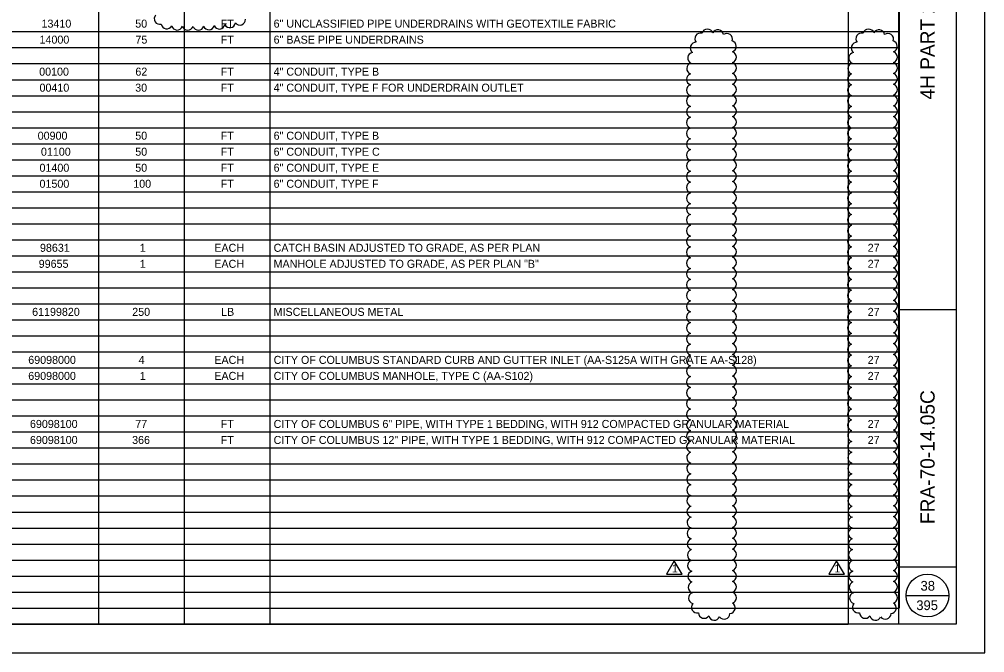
# Model space of a CAD drawing. Extents: x 0 to 34, y 0 to 22.
# Drawn here: x 17.12 to 34, y 0 to 11.08 of the extents above; entities that cross this region are included whole.
import ezdxf

# ---------------------------------------------------------------- set-up
doc = ezdxf.new("R2010")
doc.units = 0
for name, color, linetype in [('SH_Border', 7, 'Continuous'), ('SH_Cut_Line', 7, 'Continuous'), ('SH_Data', 7, 'Continuous'), ('SH_Text', 7, 'Continuous'), ('TX_P_1000', 7, 'Continuous')]:
    doc.layers.add(name, color=color, linetype=linetype)

msp = doc.modelspace()

# ---------------------------------------------------------------- linework, layer by layer
at = {"layer": 'SH_Border'}
for p, q in [((32.5, 0.5), (32.5, 21.5)), ((32.5, 6), (33.5, 6)), ((32.5, 1.5), (33.5, 1.5))]:
    msp.add_line(p, q, dxfattribs=at)
msp.add_lwpolyline([(2, 21.5), (33.5, 21.5), (33.5, 0.5), (2, 0.5)], close=True, dxfattribs=at)
at = {"layer": 'SH_Cut_Line'}
msp.add_lwpolyline([(0, 0), (34, 0), (34, 22), (0, 22)], close=True, dxfattribs=at)
at = {"layer": 'SH_Data'}
for p, q in [((18.504, 21.5), (18.504, 0.5)), ((20.002, 21.5), (20.002, 0.5)), ((21.501, 21.5), (21.501, 0.5)), ((31.614, 21.5), (31.614, 0.5)), ((32.504, 21.5), (32.504, 0.78)), ((2, 10.86), (32.504, 10.86)), ((2, 10.58), (32.504, 10.58)), ((2, 10.3), (32.504, 10.3)), ((2, 10.02), (32.504, 10.02)), ((2, 9.74), (32.504, 9.74)), ((2, 9.46), (32.504, 9.46)), ((2, 9.18), (32.504, 9.18)), ((2, 8.9), (32.504, 8.9)), ((2, 8.62), (32.504, 8.62)), ((2, 8.34), (32.504, 8.34)), ((2, 8.06), (32.504, 8.06)), ((2, 7.78), (32.504, 7.78)), ((2, 7.5), (32.504, 7.5)), ((2, 7.22), (32.504, 7.22)), ((2, 6.94), (32.504, 6.94)), ((2, 6.66), (32.504, 6.66)), ((2, 6.38), (32.504, 6.38)), ((2, 6.1), (32.504, 6.1)), ((2, 5.82), (32.504, 5.82)), ((2, 5.54), (32.504, 5.54)), ((2, 5.26), (32.504, 5.26)), ((2, 4.98), (32.504, 4.98)), ((2, 4.7), (32.504, 4.7)), ((2, 4.42), (32.504, 4.42)), ((2, 4.14), (32.504, 4.14)), ((2, 3.86), (32.504, 3.86)), ((2, 3.58), (32.504, 3.58)), ((2, 3.3), (32.504, 3.3)), ((2, 3.02), (32.504, 3.02)), ((2, 2.74), (32.504, 2.74)), ((2, 2.46), (32.504, 2.46)), ((2, 2.18), (32.504, 2.18)), ((2, 1.9), (32.504, 1.9)), ((2, 1.62), (32.504, 1.62)), ((2, 1.34), (32.504, 1.34)), ((2, 1.06), (32.504, 1.06)), ((32.625, 1), (33.375, 1)), ((2, 0.78), (32.504, 0.78)), ((2, 0.5), (31.614, 0.5))]:
    msp.add_line(p, q, dxfattribs=at)
msp.add_circle((33, 1), 0.375, dxfattribs=at)
at = {"layer": 'TX_P_1000'}
for points in [[(28.571, 1.608), (28.435, 1.372), (28.708, 1.372)], [(31.411, 1.608), (31.274, 1.372), (31.547, 1.372)]]:
    msp.add_lwpolyline(points, close=True, dxfattribs=at)
for centre, radius, start, end in [((19.578, 11.085), 0.0976, 139.2641, 284.2641), ((19.699, 11.005), 0.0976, 188.32, 333.32), ((20.62, 11.003), 0.0976, 202.8824, 347.8824), ((20.803, 11.026), 0.0976, 206.7346, 351.7346), ((20.977, 11.072), 0.0977, 217.3339, 2.3339), ((19.88, 10.986), 0.0976, 195.1082, 340.1082), ((20.065, 10.982), 0.0976, 197.1836, 342.1836), ((20.251, 10.983), 0.0976, 198.6029, 343.6029), ((20.436, 10.99), 0.0976, 200.3873, 345.3873), ((29.031, 10.736), 0.099, 74.4093, 219.4093), ((29.153, 10.805), 0.0991, 19.2496, 164.2496), ((29.336, 10.794), 0.0991, 9.041, 154.041), ((29.491, 10.729), 0.099, 340.6755, 125.6755), ((31.847, 10.736), 0.099, 74.4093, 219.4093), ((31.969, 10.805), 0.0991, 19.2496, 164.2496), ((32.152, 10.794), 0.0991, 9.041, 154.041), ((32.308, 10.729), 0.099, 340.6755, 125.6755), ((28.95, 10.574), 0.0991, 87.314, 232.314), ((29.557, 10.601), 0.0992, 288.6913, 73.6913), ((31.766, 10.574), 0.0991, 87.314, 232.314), ((32.373, 10.601), 0.0992, 288.6913, 73.6913), ((28.906, 10.398), 0.0991, 99.6335, 244.6335), ((29.559, 10.413), 0.0991, 287.5, 72.5), ((31.722, 10.398), 0.0991, 99.6335, 244.6335), ((32.375, 10.413), 0.0991, 287.5, 72.5), ((28.889, 10.213), 0.0991, 105.2456, 250.2456), ((29.559, 10.224), 0.0991, 287.5, 72.5), ((31.706, 10.213), 0.0991, 105.2456, 250.2456), ((32.375, 10.224), 0.0991, 287.5, 72.5), ((29.559, 10.035), 0.0991, 287.5, 72.5), ((32.375, 10.035), 0.0991, 287.5, 72.5), ((28.886, 10.025), 0.0991, 107.4797, 252.4797), ((31.702, 10.025), 0.0991, 107.4797, 252.4797), ((28.885, 9.836), 0.0991, 107.5, 252.5), ((29.559, 9.846), 0.0991, 287.5, 72.5), ((31.702, 9.836), 0.0991, 107.5, 252.5), ((32.375, 9.846), 0.0991, 287.5, 72.5), ((28.885, 9.647), 0.0991, 107.5, 252.5), ((29.559, 9.657), 0.0991, 287.5, 72.5), ((31.702, 9.647), 0.0991, 107.5, 252.5), ((32.375, 9.657), 0.0991, 287.5, 72.5), ((28.885, 9.458), 0.0991, 107.5, 252.5), ((29.559, 9.468), 0.0991, 287.5, 72.5), ((31.702, 9.458), 0.0991, 107.5, 252.5), ((32.375, 9.468), 0.0991, 287.5, 72.5), ((28.885, 9.269), 0.0991, 107.5, 252.5), ((29.559, 9.279), 0.0991, 287.5, 72.5), ((31.702, 9.269), 0.0991, 107.5, 252.5), ((32.375, 9.279), 0.0991, 287.5, 72.5), ((28.885, 9.08), 0.0991, 107.5, 252.5), ((29.559, 9.09), 0.0991, 287.5, 72.5), ((31.702, 9.08), 0.0991, 107.5, 252.5), ((32.375, 9.09), 0.0991, 287.5, 72.5), ((28.885, 8.891), 0.0991, 107.5, 252.5), ((29.559, 8.901), 0.0991, 287.5, 72.5), ((31.702, 8.891), 0.0991, 107.5, 252.5), ((32.375, 8.901), 0.0991, 287.5, 72.5), ((28.885, 8.702), 0.0991, 107.5, 252.5), ((29.559, 8.712), 0.0991, 287.5, 72.5), ((31.702, 8.702), 0.0991, 107.5, 252.5), ((32.375, 8.712), 0.0991, 287.5, 72.5), ((29.559, 8.523), 0.0991, 287.5, 72.5), ((32.375, 8.523), 0.0991, 287.5, 72.5), ((28.885, 8.513), 0.0991, 107.5, 252.5), ((31.702, 8.513), 0.0991, 107.5, 252.5), ((28.885, 8.324), 0.0991, 107.5, 252.5), ((29.559, 8.334), 0.0991, 287.5, 72.5), ((31.702, 8.324), 0.0991, 107.5, 252.5), ((32.375, 8.334), 0.0991, 287.5, 72.5), ((28.885, 8.135), 0.0991, 107.5, 252.5), ((29.559, 8.145), 0.0991, 287.5, 72.5), ((31.702, 8.135), 0.0991, 107.5, 252.5), ((32.375, 8.145), 0.0991, 287.5, 72.5), ((28.885, 7.946), 0.0991, 107.5, 252.5), ((29.559, 7.956), 0.0991, 287.5, 72.5), ((31.702, 7.946), 0.0991, 107.5, 252.5), ((32.375, 7.956), 0.0991, 287.5, 72.5), ((28.885, 7.757), 0.0991, 107.5, 252.5), ((29.559, 7.767), 0.0991, 287.5, 72.5), ((31.702, 7.757), 0.0991, 107.5, 252.5), ((32.375, 7.767), 0.0991, 287.5, 72.5), ((28.885, 7.568), 0.0991, 107.5, 252.5), ((29.559, 7.578), 0.0991, 287.5, 72.5), ((31.702, 7.568), 0.0991, 107.5, 252.5), ((32.375, 7.578), 0.0991, 287.5, 72.5), ((28.885, 7.379), 0.0991, 107.5, 252.5), ((29.559, 7.389), 0.0991, 287.5, 72.5), ((31.702, 7.379), 0.0991, 107.5, 252.5), ((32.375, 7.389), 0.0991, 287.5, 72.5), ((28.885, 7.19), 0.0991, 107.5, 252.5), ((29.559, 7.2), 0.0991, 287.5, 72.5), ((31.702, 7.19), 0.0991, 107.5, 252.5), ((32.375, 7.2), 0.0991, 287.5, 72.5), ((28.885, 7.001), 0.0991, 107.5, 252.5), ((29.559, 7.011), 0.0991, 287.5, 72.5), ((31.702, 7.001), 0.0991, 107.5, 252.5), ((32.375, 7.011), 0.0991, 287.5, 72.5), ((28.885, 6.812), 0.0991, 107.5, 252.5), ((29.559, 6.822), 0.0991, 287.5, 72.5), ((31.702, 6.812), 0.0991, 107.5, 252.5), ((32.375, 6.822), 0.0991, 287.5, 72.5), ((28.885, 6.623), 0.0991, 107.5, 252.5), ((29.559, 6.633), 0.0991, 287.5, 72.5), ((31.702, 6.623), 0.0991, 107.5, 252.5), ((32.375, 6.633), 0.0991, 287.5, 72.5), ((28.885, 6.434), 0.0991, 107.5, 252.5), ((29.559, 6.444), 0.0991, 287.5, 72.5), ((31.702, 6.434), 0.0991, 107.5, 252.5), ((32.375, 6.444), 0.0991, 287.5, 72.5), ((28.885, 6.245), 0.0991, 107.5, 252.5), ((29.559, 6.255), 0.0991, 287.5, 72.5), ((31.702, 6.245), 0.0991, 107.5, 252.5), ((32.375, 6.255), 0.0991, 287.5, 72.5), ((28.885, 6.056), 0.0991, 107.5, 252.5), ((29.559, 6.066), 0.0991, 287.5, 72.5), ((31.702, 6.056), 0.0991, 107.5, 252.5), ((32.375, 6.066), 0.0991, 287.5, 72.5), ((28.885, 5.867), 0.0991, 107.5, 252.5), ((29.559, 5.877), 0.0991, 287.5, 72.5), ((31.702, 5.867), 0.0991, 107.5, 252.5), ((32.375, 5.877), 0.0991, 287.5, 72.5), ((28.885, 5.678), 0.0991, 107.5, 252.5), ((29.559, 5.688), 0.0991, 287.5, 72.5), ((31.702, 5.678), 0.0991, 107.5, 252.5), ((32.375, 5.688), 0.0991, 287.5, 72.5), ((28.885, 5.489), 0.0991, 107.5, 252.5), ((29.559, 5.499), 0.0991, 287.5, 72.5), ((31.702, 5.489), 0.0991, 107.5, 252.5), ((32.375, 5.499), 0.0991, 287.5, 72.5), ((29.559, 5.31), 0.0991, 287.5, 72.5), ((32.375, 5.31), 0.0991, 287.5, 72.5), ((28.885, 5.3), 0.0991, 107.5, 252.5), ((31.702, 5.3), 0.0991, 107.5, 252.5), ((28.886, 5.111), 0.0991, 107.5091, 252.5091), ((29.559, 5.121), 0.0991, 287.5, 72.5), ((31.702, 5.111), 0.0991, 107.5091, 252.5091), ((32.375, 5.121), 0.0991, 287.5, 72.5), ((28.886, 4.922), 0.0991, 107.5258, 252.5258), ((29.559, 4.932), 0.0991, 287.5, 72.5), ((31.702, 4.922), 0.0991, 107.5258, 252.5258), ((32.375, 4.932), 0.0991, 287.5, 72.5), ((28.886, 4.733), 0.0991, 107.5437, 252.5437), ((29.559, 4.743), 0.0991, 287.5, 72.5), ((31.702, 4.733), 0.0991, 107.5437, 252.5437), ((32.375, 4.743), 0.0991, 287.5, 72.5), ((28.886, 4.544), 0.0991, 107.5629, 252.5629), ((29.559, 4.554), 0.0991, 287.5, 72.5), ((31.702, 4.544), 0.0991, 107.5629, 252.5629), ((32.375, 4.554), 0.0991, 287.5, 72.5), ((28.886, 4.355), 0.0991, 107.5836, 252.5836), ((29.559, 4.365), 0.0991, 287.5, 72.5), ((31.703, 4.355), 0.0991, 107.5836, 252.5836), ((32.375, 4.365), 0.0991, 287.5, 72.5), ((28.886, 4.166), 0.0991, 107.606, 252.606), ((29.559, 4.176), 0.0991, 287.5, 72.5), ((31.703, 4.166), 0.0991, 107.606, 252.606), ((32.375, 4.176), 0.0991, 287.5, 72.5), ((28.887, 3.977), 0.0991, 107.6303, 252.6303), ((29.559, 3.987), 0.0991, 287.5, 72.5), ((31.703, 3.977), 0.0991, 107.6303, 252.6303), ((32.375, 3.987), 0.0991, 287.5, 72.5), ((28.887, 3.788), 0.0991, 107.6568, 252.6568), ((29.559, 3.797), 0.0991, 287.5, 72.5), ((31.704, 3.788), 0.0991, 107.6568, 252.6568), ((32.375, 3.797), 0.0991, 287.5, 72.5), ((28.888, 3.599), 0.0991, 107.6859, 252.6859), ((29.559, 3.608), 0.0991, 287.5, 72.5), ((31.704, 3.599), 0.0991, 107.6859, 252.6859), ((32.375, 3.608), 0.0991, 287.5, 72.5), ((28.889, 3.41), 0.0991, 107.718, 252.718), ((29.559, 3.419), 0.0991, 287.5, 72.5), ((31.705, 3.41), 0.0991, 107.718, 252.718), ((32.375, 3.419), 0.0991, 287.5, 72.5), ((28.889, 3.221), 0.0991, 107.7537, 252.7537), ((29.559, 3.23), 0.0991, 287.5, 72.5), ((31.706, 3.221), 0.0991, 107.7537, 252.7537), ((32.375, 3.23), 0.0991, 287.5, 72.5), ((28.89, 3.032), 0.0991, 107.7938, 252.7938), ((29.559, 3.041), 0.0991, 287.5, 72.5), ((31.707, 3.032), 0.0991, 107.7938, 252.7938), ((32.375, 3.041), 0.0991, 287.5, 72.5), ((28.891, 2.843), 0.0991, 107.8391, 252.8391), ((29.559, 2.852), 0.0991, 287.5, 72.5), ((31.708, 2.843), 0.0991, 107.8391, 252.8391), ((32.375, 2.852), 0.0991, 287.5, 72.5), ((28.892, 2.654), 0.0991, 107.8909, 252.8909), ((29.559, 2.663), 0.0991, 287.5, 72.5), ((31.709, 2.654), 0.0991, 107.8909, 252.8909), ((32.375, 2.663), 0.0991, 287.5, 72.5), ((28.894, 2.465), 0.0991, 107.951, 252.951), ((29.559, 2.474), 0.0991, 287.5, 72.5), ((31.71, 2.465), 0.0991, 107.951, 252.951), ((32.375, 2.474), 0.0991, 287.5, 72.5), ((28.895, 2.276), 0.0991, 108.0219, 253.0219), ((29.559, 2.285), 0.0991, 287.5, 72.5), ((31.712, 2.276), 0.0991, 108.0219, 253.0219), ((32.375, 2.285), 0.0991, 287.5, 72.5), ((28.897, 2.087), 0.0991, 108.1071, 253.1071), ((29.559, 2.096), 0.0991, 287.5, 72.5), ((31.714, 2.087), 0.0991, 108.1071, 253.1071), ((32.375, 2.096), 0.0991, 287.5, 72.5), ((28.899, 1.898), 0.0991, 108.2123, 253.2123), ((29.559, 1.907), 0.0991, 287.5, 72.5), ((31.716, 1.898), 0.0991, 108.2123, 253.2123), ((32.375, 1.907), 0.0991, 287.5, 72.5), ((28.902, 1.709), 0.0991, 108.3469, 253.3469), ((29.559, 1.718), 0.0991, 287.5, 72.5), ((31.719, 1.709), 0.0991, 108.3469, 253.3469), ((32.375, 1.718), 0.0991, 287.5, 72.5), ((28.905, 1.521), 0.0991, 108.5276, 253.5276), ((29.559, 1.529), 0.0991, 287.5, 72.5), ((31.722, 1.521), 0.0991, 108.5276, 253.5276), ((32.375, 1.529), 0.0991, 287.5, 72.5), ((28.909, 1.332), 0.0991, 108.7891, 253.7891), ((29.559, 1.34), 0.0991, 287.5, 72.5), ((31.725, 1.332), 0.0991, 108.7891, 253.7891), ((32.375, 1.34), 0.0991, 287.5, 72.5), ((28.914, 1.143), 0.0991, 109.2189, 254.2189), ((29.559, 1.151), 0.0991, 287.5, 72.5), ((31.73, 1.143), 0.0991, 109.2189, 254.2189), ((32.375, 1.151), 0.0991, 287.5, 72.5), ((28.921, 0.955), 0.0991, 110.1571, 255.1571), ((29.559, 0.962), 0.0991, 287.5, 72.5), ((31.738, 0.955), 0.0991, 110.1571, 255.1571), ((32.375, 0.962), 0.0991, 287.5, 72.5), ((28.971, 0.794), 0.0991, 139.2663, 284.2663), ((29.538, 0.783), 0.0991, 274.2898, 59.2898), ((31.787, 0.794), 0.0991, 139.2663, 284.2663), ((32.354, 0.783), 0.0991, 274.2898, 59.2898), ((29.094, 0.7), 0.0991, 180.783, 325.783), ((29.446, 0.685), 0.0991, 214.5703, 359.5703), ((31.911, 0.7), 0.0991, 180.783, 325.783), ((32.263, 0.685), 0.0991, 214.5703, 359.5703), ((29.273, 0.666), 0.0991, 192.8167, 337.8167), ((32.089, 0.666), 0.0991, 192.8167, 337.8167)]:
    msp.add_arc(centre, radius, start, end, dxfattribs=at)

# ---------------------------------------------------------------- texts
at = {"layer": 'SH_Data'}
for s, p in [('4H PART 2 GENERAL SUMMARY', (33.125, 9.672)), ('FRA-70-14.05C', (33.125, 2.249))]:
    msp.add_text(s, height=0.25, rotation=90, dxfattribs=at).set_placement(p)
at = {"layer": 'SH_Text'}
for s, height, p in [('13410', 0.14, (17.509, 10.93)), ('50', 0.14, (19.148, 10.93)), ('FT', 0.14, (20.642, 10.93)), ('6" UNCLASSIFIED PIPE UNDERDRAINS WITH GEOTEXTILE FABRIC', 0.14, (21.567, 10.93)), ('14000', 0.14, (17.474, 10.65)), ('75', 0.14, (19.151, 10.65)), ('FT', 0.14, (20.642, 10.65)), ('6" BASE PIPE UNDERDRAINS ', 0.14, (21.567, 10.65)), ('00100', 0.14, (17.468, 10.09)), ('62', 0.14, (19.15, 10.09)), ('FT', 0.14, (20.642, 10.09)), ('4" CONDUIT, TYPE B', 0.14, (21.567, 10.09)), ('00410', 0.14, (17.474, 9.81)), ('30', 0.14, (19.147, 9.81)), ('FT', 0.14, (20.642, 9.81)), ('4" CONDUIT, TYPE F FOR UNDERDRAIN OUTLET', 0.14, (21.567, 9.81)), ('00900', 0.14, (17.442, 8.97)), ('50', 0.14, (19.148, 8.97)), ('FT', 0.14, (20.642, 8.97)), ('6" CONDUIT, TYPE B', 0.14, (21.567, 8.97)), ('01100', 0.14, (17.499, 8.69)), ('50', 0.14, (19.148, 8.69)), ('FT', 0.14, (20.642, 8.69)), ('6" CONDUIT, TYPE C', 0.14, (21.567, 8.69)), ('01400', 0.14, (17.474, 8.41)), ('50', 0.14, (19.148, 8.41)), ('FT', 0.14, (20.642, 8.41)), ('6" CONDUIT, TYPE E', 0.14, (21.567, 8.41)), ('01500', 0.14, (17.474, 8.13)), ('100', 0.14, (19.113, 8.13)), ('6" CONDUIT, TYPE F', 0.14, (21.567, 8.13)), ('FT', 0.14, (20.642, 8.13)), ('98631', 0.14, (17.482, 7.01)), ('1', 0.14, (19.227, 7.01)), ('EACH', 0.14, (20.53, 7.01)), ('CATCH BASIN ADJUSTED TO GRADE, AS PER PLAN', 0.14, (21.567, 7.01)), ('27', 0.14, (31.954, 7.01)), ('99655', 0.14, (17.46, 6.73)), ('1', 0.14, (19.227, 6.73)), ('EACH', 0.14, (20.53, 6.73)), ('MANHOLE ADJUSTED TO GRADE, AS PER PLAN "B"', 0.14, (21.567, 6.73)), ('27', 0.14, (31.954, 6.73)), ('61199820', 0.14, (17.345, 5.89)), ('250', 0.14, (19.095, 5.89)), ('LB', 0.14, (20.649, 5.89)), ('MISCELLANEOUS METAL', 0.14, (21.567, 5.89)), ('27', 0.14, (31.954, 5.89)), ('69098000', 0.14, (17.277, 5.05)), ('4', 0.14, (19.206, 5.05)), ('EACH', 0.14, (20.53, 5.05)), ('CITY OF COLUMBUS STANDARD CURB AND GUTTER INLET (AA-S125A WITH GRATE AA-S128)', 0.14, (21.567, 5.05)), ('27', 0.14, (31.954, 5.05)), ('69098000', 0.14, (17.277, 4.77)), ('1', 0.14, (19.227, 4.77)), ('EACH', 0.14, (20.53, 4.77)), ('CITY OF COLUMBUS MANHOLE, TYPE C (AA-S102)', 0.14, (21.567, 4.77)), ('27', 0.14, (31.954, 4.77)), ('69098100', 0.14, (17.307, 3.93)), ('77', 0.14, (19.148, 3.93)), ('FT', 0.14, (20.642, 3.93)), ('CITY OF COLUMBUS 6" PIPE, WITH TYPE 1 BEDDING, WITH 912 COMPACTED GRANULAR MATERIAL', 0.14, (21.567, 3.93)), ('27', 0.14, (31.954, 3.93)), ('69098100', 0.14, (17.307, 3.65)), ('366', 0.14, (19.093, 3.65)), ('FT', 0.14, (20.642, 3.65)), ('CITY OF COLUMBUS 12" PIPE, WITH TYPE 1 BEDDING, WITH 912 COMPACTED GRANULAR MATERIAL', 0.14, (21.567, 3.65)), ('27', 0.14, (31.954, 3.65)), ('38', 0.17, (32.878, 1.085)), ('395', 0.17, (32.804, 0.745))]:
    msp.add_text(s, height=height, dxfattribs=at).set_placement(p)
at = {"layer": 'TX_P_1000'}
for p in [(28.532, 1.403), (31.372, 1.403)]:
    msp.add_text('1', height=0.14, rotation=360, dxfattribs=at).set_placement(p)

doc.saveas('drawing.dxf')
